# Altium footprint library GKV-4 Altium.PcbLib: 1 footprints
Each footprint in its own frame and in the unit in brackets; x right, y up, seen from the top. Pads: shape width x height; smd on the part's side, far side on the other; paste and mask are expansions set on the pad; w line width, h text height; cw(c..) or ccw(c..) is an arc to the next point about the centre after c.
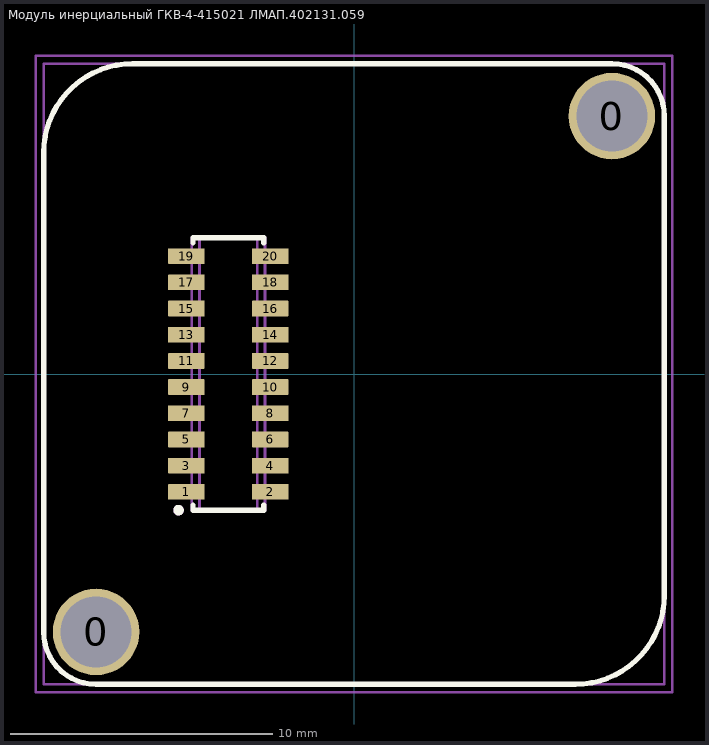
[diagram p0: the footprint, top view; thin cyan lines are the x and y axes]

## Модуль инерциальный ГКВ-4-415021 ЛМАП.402131.059 [mm]
height 10
pads (22):
  round 3.3 / inner round 5.5 / far side round 5.5 hole 2.7: 0(-9.85,-9.85) 0(9.85,9.85)
  rrect10% 1.4x0.6 smd: 1(-6.4,-4.5) 2(-3.2,-4.5) 3(-6.4,-3.5) 4(-3.2,-3.5) 5(-6.4,-2.5) 6(-3.2,-2.5) 7(-6.4,-1.5) 8(-3.2,-1.5) 9(-6.4,-0.5) 10(-3.2,-0.5) 11(-6.4,0.5) 12(-3.2,0.5) 13(-6.4,1.5) 14(-3.2,1.5) 15(-6.4,2.5) 16(-3.2,2.5) 17(-6.4,3.5) 18(-3.2,3.5) 19(-6.4,4.5) 20(-3.2,4.5)
Top Layer:
  lines w0.17: -6.41,1.51 -6.4,1.5 ; -6.4,-2.5 -6.4,-2.5 ; -3.2,-2.5 -3.2,-2.5 ; -6.4,-4.5 -6.4,-4.5 ; -6.4,-1.5 -6.4,-1.5 ; -6.4,-0.5 -6.4,-0.5 ; -6.4,3.5 -6.4,3.5 ; -3.2,-4.5 -3.2,-4.5 ; -3.2,1.5 -3.2,1.5 ; -3.2,2.5 -3.2,2.5 ; -3.2,3.5 -3.2,3.5
  lines w0.4: -6.405,0.495 -6.4,0.5 ; -3.2,-0.5 -3.2,-0.5 ; -3.2,0.5 -3.2,0.5
Top Overlay:
  circle w0.2: c-6.7,-5.2 r0.1
  lines w0.2: -6.15,-5 -6.15,-5.2 -3.45,-5.2 -3.45,-5 ; -6.15,5 -6.15,5.2 -3.45,5.2 -3.45,5 ; -11.85,-9.85 ccw(c-9.85,-9.85) -9.85,-11.85 8.45,-11.85 ccw(c8.45,-8.45) 11.85,-8.45 11.85,9.85 ccw(c9.85,9.85) 9.85,11.85 -8.45,11.85 ccw(c-8.45,8.45) -11.85,8.45 -11.85,-9.85
Mechanical 1:
  lines w0.1: -11.85,-11.85 -11.85,11.85 11.85,11.85 11.85,-11.85 -11.85,-11.85
Mechanical 13:
  circle w0.1: c-6.7,-5.2 r0.15
  circle w0.1: c9.85,9.85 r1.275
  circle w0.1: c-9.85,-9.85 r1.275
  lines w0.1: -6.2,-4.7 -6.7,-4.7 -6.7,-4.3 -6.2,-4.3 ; -6.2,-3.7 -6.7,-3.7 -6.7,-3.3 -6.2,-3.3 ; -6.2,-2.7 -6.7,-2.7 -6.7,-2.3 -6.2,-2.3 ; -6.2,-1.7 -6.7,-1.7 -6.7,-1.3 -6.2,-1.3 ; -6.2,-0.7 -6.7,-0.7 -6.7,-0.3 -6.2,-0.3 ; -6.2,0.3 -6.7,0.3 -6.7,0.7 -6.2,0.7 ; -6.2,1.3 -6.7,1.3 -6.7,1.7 -6.2,1.7 ; -6.2,2.3 -6.7,2.3 -6.7,2.7 -6.2,2.7 ; -6.2,3.3 -6.7,3.3 -6.7,3.7 -6.2,3.7 ; -6.2,4.3 -6.7,4.3 -6.7,4.7 -6.2,4.7 ; -5.9,-5.2 -5.9,5.2 ; -3.7,-5.2 -3.7,5.2 ; -3.4,-4.7 -2.9,-4.7 -2.9,-4.3 -3.4,-4.3 ; -3.4,-3.7 -2.9,-3.7 -2.9,-3.3 -3.4,-3.3 ; -3.4,-2.7 -2.9,-2.7 -2.9,-2.3 -3.4,-2.3 ; -3.4,-1.7 -2.9,-1.7 -2.9,-1.3 -3.4,-1.3 ; -3.4,-0.7 -2.9,-0.7 -2.9,-0.3 -3.4,-0.3 ; -3.4,0.3 -2.9,0.3 -2.9,0.7 -3.4,0.7 ; -3.4,1.3 -2.9,1.3 -2.9,1.7 -3.4,1.7 ; -3.4,2.3 -2.9,2.3 -2.9,2.7 -3.4,2.7 ; -3.4,3.3 -2.9,3.3 -2.9,3.7 -3.4,3.7 ; -3.4,4.3 -2.9,4.3 -2.9,4.7 -3.4,4.7 ; -11.85,-9.85 ccw(c-9.85,-9.85) -9.85,-11.85 8.45,-11.85 ccw(c8.45,-8.45) 11.85,-8.45 11.85,9.85 ccw(c9.85,9.85) 9.85,11.85 -8.45,11.85 ccw(c-8.45,8.45) -11.85,8.45 -11.85,-9.85 ; -6.2,-5.2 -3.4,-5.2 -3.4,5.2 -6.2,5.2 -6.2,-5.2
  text ".Designator" at -1.428,-0.2 h1
Mechanical 15:
  lines w0.1: -12.15,-12.15 -12.15,12.15 12.15,12.15 12.15,-12.15 -12.15,-12.15
3D body "ЛМАП.402131.059 Инерциальный модуль ГКВ-4.STEP": height 10, standoff 0, extent -11.85,-11.85 11.85,11.85
3D body "clm-110-02-h-d.stp": height 2.26, standoff 0.01, extent -6.705,-5.161 -2.895,5.156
